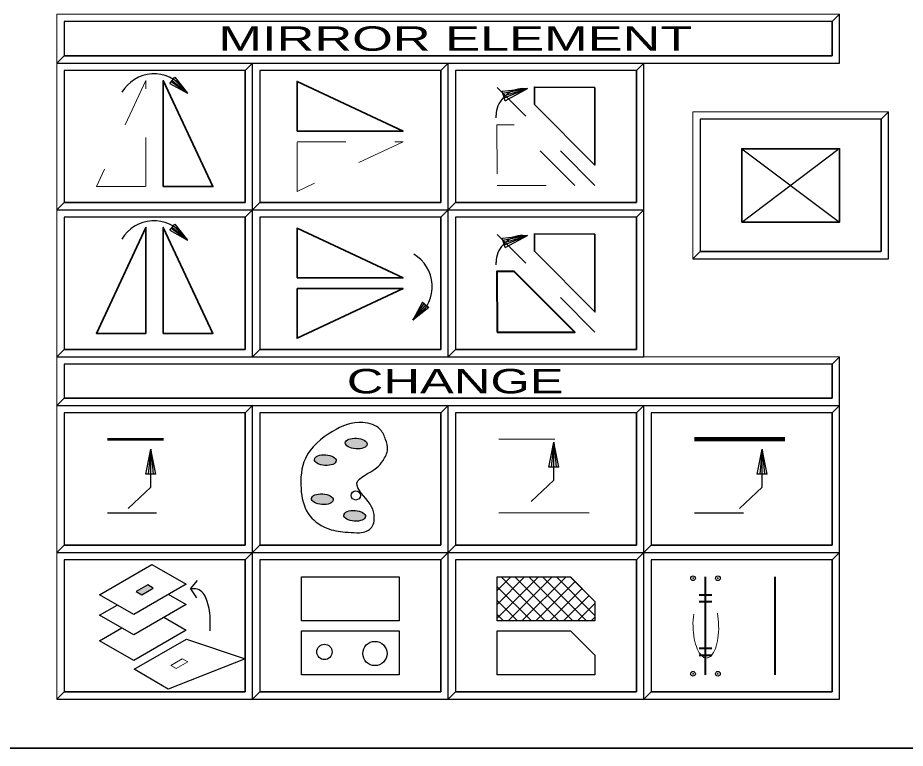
# Model space of a CAD drawing. Extents: x 95906.8 to 95923.6, y 90964.8 to 90972.8.
# Drawn here: x 95912.552 to 95914.367, y 90964.762 to 90966.254 of the extents above; entities that cross this region are included whole.
import ezdxf
from ezdxf.enums import TextEntityAlignment as Align

# ---------------------------------------------------------------- set-up
doc = ezdxf.new("R2010")
doc.units = 0
doc.header["$LTSCALE"] = 0.019
doc.header["$PDMODE"] = 32
doc.header["$PDSIZE"] = 0.0095
doc.linetypes.add('LONG_DASHED', pattern=[7.5, 6, -1.5])
doc.linetypes.add('MEDIUM_DASHED', pattern=[4.5, 3, -1.5])
for name, color, linetype, lineweight in [('11', 7, 'Continuous', 25), ('12', 7, 'Continuous', 25), ('16', 7, 'Continuous', 25), ('18', 7, 'Continuous', 25), ('2', 7, 'Continuous', 13), ('3', 7, 'Continuous', 25), ('6', 7, 'Continuous', 25), ('7', 7, 'Continuous', 35)]:
    doc.layers.add(name, color=color, linetype=linetype, lineweight=lineweight)

msp = doc.modelspace()

# ---------------------------------------------------------------- hatches: boundary and pattern name
at = {"layer": '6'}
h = msp.add_hatch(color=256, dxfattribs=at)
edge = h.paths.add_edge_path()
edge.add_ellipse((95913.2443, 90965.3842), major_axis=(-0.0223, 0.0015), ratio=0.490241, start_angle=0, end_angle=360)
h = msp.add_hatch(color=256, dxfattribs=at)
edge = h.paths.add_edge_path()
edge.add_ellipse((95913.1812, 90965.3504), major_axis=(-0.0223, 0.0015), ratio=0.490241, start_angle=0, end_angle=360)
h = msp.add_hatch(color=256, dxfattribs=at)
edge = h.paths.add_edge_path()
edge.add_ellipse((95913.1751, 90965.2705), major_axis=(-0.0223, 0.0015), ratio=0.490241, start_angle=0, end_angle=360)
h = msp.add_hatch(color=256, dxfattribs=at)
edge = h.paths.add_edge_path()
edge.add_ellipse((95913.2412, 90965.2366), major_axis=(-0.0223, 0.0015), ratio=0.490241, start_angle=0, end_angle=360)
msp.add_hatch(color=256, dxfattribs=at).paths.add_polyline_path([(95912.8058, 90965.0753), (95912.8293, 90965.0889), (95912.8181, 90965.0953), (95912.7946, 90965.0817)])

# ---------------------------------------------------------------- linework, layer by layer
at = {"layer": '11'}
for points in [[(95913.0473, 90965.8767), (95913.4173, 90965.8767), (95913.4173, 90966.1467), (95913.0473, 90966.1467)], [(95913.4473, 90965.8767), (95913.8173, 90965.8767), (95913.8173, 90966.1467), (95913.4473, 90966.1467)], [(95912.6473, 90965.5767), (95913.0173, 90965.5767), (95913.0173, 90965.8467), (95912.6473, 90965.8467)], [(95913.0473, 90965.5767), (95913.4173, 90965.5767), (95913.4173, 90965.8467), (95913.0473, 90965.8467)], [(95913.4473, 90965.5767), (95913.8173, 90965.5767), (95913.8173, 90965.8467), (95913.4473, 90965.8467)], [(95912.6473, 90965.1767), (95913.0173, 90965.1767), (95913.0173, 90965.4467), (95912.6473, 90965.4467)], [(95913.0473, 90965.1767), (95913.4173, 90965.1767), (95913.4173, 90965.4467), (95913.0473, 90965.4467)], [(95913.4473, 90965.1767), (95913.8173, 90965.1767), (95913.8173, 90965.4467), (95913.4473, 90965.4467)], [(95912.6473, 90964.8767), (95913.0173, 90964.8767), (95913.0173, 90965.1467), (95912.6473, 90965.1467)], [(95913.0473, 90964.8767), (95913.4173, 90964.8767), (95913.4173, 90965.1467), (95913.0473, 90965.1467)], [(95913.4473, 90964.8767), (95913.8173, 90964.8767), (95913.8173, 90965.1467), (95913.4473, 90965.1467)], [(95913.8473, 90964.8767), (95914.2173, 90964.8767), (95914.2173, 90965.1467), (95913.8473, 90965.1467)]]:
    msp.add_lwpolyline(points, close=True, dxfattribs=at)
at = {"layer": '12'}
for points in [[(95912.6473, 90965.8767), (95913.0173, 90965.8767), (95913.0173, 90966.1467), (95912.6473, 90966.1467)], [(95913.8473, 90965.1767), (95914.2173, 90965.1767), (95914.2173, 90965.4467), (95913.8473, 90965.4467)]]:
    msp.add_lwpolyline(points, close=True, dxfattribs=at)
at = {"layer": '16'}
msp.add_lwpolyline([(95913.9473, 90965.7767), (95914.3173, 90965.7767), (95914.3173, 90966.0467), (95913.9473, 90966.0467)], close=True, dxfattribs=at)
at = {"layer": '18'}
for points in [[(95912.6473, 90966.1767), (95914.2173, 90966.1767), (95914.2173, 90966.2467), (95912.6473, 90966.2467)], [(95912.6473, 90965.4767), (95914.2173, 90965.4767), (95914.2173, 90965.5467), (95912.6473, 90965.5467)]]:
    msp.add_lwpolyline(points, close=True, dxfattribs=at)
at = {"layer": '2'}
for points in [[(95912.6323, 90966.2617), (95912.6323, 90966.1617), (95912.6473, 90966.1767), (95912.6473, 90966.2467), (95914.2173, 90966.2467), (95914.2323, 90966.2617)], [(95912.6323, 90966.1617), (95912.6323, 90965.8617), (95912.6473, 90965.8767), (95912.6473, 90966.1467), (95913.0173, 90966.1467), (95913.0323, 90966.1617)], [(95913.0323, 90966.1617), (95913.0323, 90965.8617), (95913.0473, 90965.8767), (95913.0473, 90966.1467), (95913.4173, 90966.1467), (95913.4323, 90966.1617)], [(95913.4323, 90966.1617), (95913.4323, 90965.8617), (95913.4473, 90965.8767), (95913.4473, 90966.1467), (95913.8173, 90966.1467), (95913.8323, 90966.1617)], [(95913.9323, 90966.0617), (95913.9323, 90965.7617), (95913.9473, 90965.7767), (95913.9473, 90966.0467), (95914.3173, 90966.0467), (95914.3323, 90966.0617)], [(95912.6323, 90965.8617), (95912.6323, 90965.5617), (95912.6473, 90965.5767), (95912.6473, 90965.8467), (95913.0173, 90965.8467), (95913.0323, 90965.8617)], [(95913.0323, 90965.8617), (95913.0323, 90965.5617), (95913.0473, 90965.5767), (95913.0473, 90965.8467), (95913.4173, 90965.8467), (95913.4323, 90965.8617)], [(95913.4323, 90965.8617), (95913.4323, 90965.5617), (95913.4473, 90965.5767), (95913.4473, 90965.8467), (95913.8173, 90965.8467), (95913.8323, 90965.8617)], [(95912.6323, 90965.5617), (95912.6323, 90965.4617), (95912.6473, 90965.4767), (95912.6473, 90965.5467), (95914.2173, 90965.5467), (95914.2323, 90965.5617)], [(95912.6323, 90965.4617), (95912.6323, 90965.1617), (95912.6473, 90965.1767), (95912.6473, 90965.4467), (95913.0173, 90965.4467), (95913.0323, 90965.4617)], [(95913.0323, 90965.4617), (95913.0323, 90965.1617), (95913.0473, 90965.1767), (95913.0473, 90965.4467), (95913.4173, 90965.4467), (95913.4323, 90965.4617)], [(95913.4323, 90965.4617), (95913.4323, 90965.1617), (95913.4473, 90965.1767), (95913.4473, 90965.4467), (95913.8173, 90965.4467), (95913.8323, 90965.4617)], [(95913.8323, 90965.4617), (95913.8323, 90965.1617), (95913.8473, 90965.1767), (95913.8473, 90965.4467), (95914.2173, 90965.4467), (95914.2323, 90965.4617)], [(95912.6323, 90965.1617), (95912.6323, 90964.8617), (95912.6473, 90964.8767), (95912.6473, 90965.1467), (95913.0173, 90965.1467), (95913.0323, 90965.1617)], [(95913.0323, 90965.1617), (95913.0323, 90964.8617), (95913.0473, 90964.8767), (95913.0473, 90965.1467), (95913.4173, 90965.1467), (95913.4323, 90965.1617)], [(95913.4323, 90965.1617), (95913.4323, 90964.8617), (95913.4473, 90964.8767), (95913.4473, 90965.1467), (95913.8173, 90965.1467), (95913.8323, 90965.1617)], [(95913.8323, 90965.1617), (95913.8323, 90964.8617), (95913.8473, 90964.8767), (95913.8473, 90965.1467), (95914.2173, 90965.1467), (95914.2323, 90965.1617)]]:
    msp.add_lwpolyline(points, close=True, dxfattribs=at)
at = {"layer": '3'}
for points in [[(95912.6323, 90966.1617), (95914.2323, 90966.1617), (95914.2323, 90966.2617), (95914.2173, 90966.2467), (95914.2173, 90966.1767), (95912.6473, 90966.1767)], [(95912.6323, 90965.8617), (95913.0323, 90965.8617), (95913.0323, 90966.1617), (95913.0173, 90966.1467), (95913.0173, 90965.8767), (95912.6473, 90965.8767)], [(95913.0323, 90965.8617), (95913.4323, 90965.8617), (95913.4323, 90966.1617), (95913.4173, 90966.1467), (95913.4173, 90965.8767), (95913.0473, 90965.8767)], [(95913.4323, 90965.8617), (95913.8323, 90965.8617), (95913.8323, 90966.1617), (95913.8173, 90966.1467), (95913.8173, 90965.8767), (95913.4473, 90965.8767)], [(95913.9323, 90965.7617), (95914.3323, 90965.7617), (95914.3323, 90966.0617), (95914.3173, 90966.0467), (95914.3173, 90965.7767), (95913.9473, 90965.7767)], [(95912.6323, 90965.5617), (95913.0323, 90965.5617), (95913.0323, 90965.8617), (95913.0173, 90965.8467), (95913.0173, 90965.5767), (95912.6473, 90965.5767)], [(95913.0323, 90965.5617), (95913.4323, 90965.5617), (95913.4323, 90965.8617), (95913.4173, 90965.8467), (95913.4173, 90965.5767), (95913.0473, 90965.5767)], [(95913.4323, 90965.5617), (95913.8323, 90965.5617), (95913.8323, 90965.8617), (95913.8173, 90965.8467), (95913.8173, 90965.5767), (95913.4473, 90965.5767)], [(95912.6323, 90965.4617), (95914.2323, 90965.4617), (95914.2323, 90965.5617), (95914.2173, 90965.5467), (95914.2173, 90965.4767), (95912.6473, 90965.4767)], [(95912.6323, 90965.1617), (95913.0323, 90965.1617), (95913.0323, 90965.4617), (95913.0173, 90965.4467), (95913.0173, 90965.1767), (95912.6473, 90965.1767)], [(95913.0323, 90965.1617), (95913.4323, 90965.1617), (95913.4323, 90965.4617), (95913.4173, 90965.4467), (95913.4173, 90965.1767), (95913.0473, 90965.1767)], [(95913.4323, 90965.1617), (95913.8323, 90965.1617), (95913.8323, 90965.4617), (95913.8173, 90965.4467), (95913.8173, 90965.1767), (95913.4473, 90965.1767)], [(95913.8323, 90965.1617), (95914.2323, 90965.1617), (95914.2323, 90965.4617), (95914.2173, 90965.4467), (95914.2173, 90965.1767), (95913.8473, 90965.1767)], [(95912.6323, 90964.8617), (95913.0323, 90964.8617), (95913.0323, 90965.1617), (95913.0173, 90965.1467), (95913.0173, 90964.8767), (95912.6473, 90964.8767)], [(95913.0323, 90964.8617), (95913.4323, 90964.8617), (95913.4323, 90965.1617), (95913.4173, 90965.1467), (95913.4173, 90964.8767), (95913.0473, 90964.8767)], [(95913.4323, 90964.8617), (95913.8323, 90964.8617), (95913.8323, 90965.1617), (95913.8173, 90965.1467), (95913.8173, 90964.8767), (95913.4473, 90964.8767)], [(95913.8323, 90964.8617), (95914.2323, 90964.8617), (95914.2323, 90965.1617), (95914.2173, 90965.1467), (95914.2173, 90964.8767), (95913.8473, 90964.8767)]]:
    msp.add_lwpolyline(points, close=True, dxfattribs=at)
at = {"layer": '6'}
for p, q in [((95912.8997, 90966.0999), (95912.8659, 90966.1233)), ((95912.8683, 90966.1262), (95912.8997, 90966.0999)), ((95913.5457, 90966.0944), (95913.5947, 90966.1094)), ((95913.5947, 90966.1094), (95913.5471, 90966.0899)), ((95913.5846, 90966.1094), (95913.5947, 90966.1094)), ((95913.5447, 90966.0902), (95913.5493, 90966.0948)), ((95913.5301, 90966.0495), (95913.5301, 90966.0549)), ((95914.0323, 90965.9867), (95914.2323, 90965.8367)), ((95914.0323, 90965.8367), (95914.2287, 90965.9852)), ((95912.8997, 90965.7999), (95912.8659, 90965.8233)), ((95912.8683, 90965.8262), (95912.8997, 90965.7999)), ((95913.5457, 90965.7944), (95913.5947, 90965.8094)), ((95913.5947, 90965.8094), (95913.5471, 90965.7899)), ((95913.5846, 90965.8094), (95913.5947, 90965.8094)), ((95913.5447, 90965.7902), (95913.5493, 90965.7948)), ((95913.5301, 90965.7495), (95913.5301, 90965.7549)), ((95913.36, 90965.6364), (95913.3834, 90965.6702)), ((95913.3863, 90965.6678), (95913.36, 90965.6364)), ((95913.6481, 90965.3361), (95913.6481, 90965.3873)), ((95913.6481, 90965.3873), (95913.6529, 90965.3361)), ((95912.8242, 90965.3216), (95912.8242, 90965.3728)), ((95912.8242, 90965.3728), (95912.829, 90965.3216)), ((95914.0742, 90965.3216), (95914.0742, 90965.3728)), ((95914.0742, 90965.3728), (95914.079, 90965.3216)), ((95912.9057, 90965.0875), (95912.9196, 90965.1044)), ((95912.9057, 90965.0875), (95912.918, 90965.0691)), ((95912.9124, 90965.0875), (95912.9057, 90965.0875)), ((95912.938, 90965.0659), (95912.9353, 90965.0725)), ((95912.9457, 90965.0014), (95912.9457, 90965.0275))]:
    msp.add_line(p, q, dxfattribs=at)
at = {"layer": '6', "linetype": 'MEDIUM_DASHED', "lineweight": 13}
for p, q in [((95913.7323, 90965.9117), (95913.5323, 90966.1117)), ((95913.7323, 90965.6117), (95913.5323, 90965.8117))]:
    msp.add_line(p, q, dxfattribs=at)
at = {"layer": '6', "linetype": 'LONG_DASHED', "lineweight": 53}
msp.add_line((95912.7361, 90965.393), (95912.9205, 90965.393), dxfattribs=at)
at = {"layer": '6', "linetype": 'LONG_DASHED', "lineweight": 13}
msp.add_line((95913.5361, 90965.393), (95913.7205, 90965.393), dxfattribs=at)
at = {"layer": '6', "lineweight": 158}
msp.add_line((95913.9361, 90965.393), (95914.1205, 90965.393), dxfattribs=at)
at = {"layer": '6', "linetype": 'MEDIUM_DASHED'}
for p, q in [((95912.7361, 90965.2424), (95912.9205, 90965.2424)), ((95913.9361, 90965.2424), (95914.1205, 90965.2424))]:
    msp.add_line(p, q, dxfattribs=at)
at = {"layer": '6', "lineweight": 13}
for p, q in [((95913.5361, 90965.2424), (95913.7205, 90965.2424)), ((95913.5323, 90965.0273), (95913.6167, 90965.1117)), ((95913.5323, 90965.0556), (95913.5884, 90965.1117)), ((95913.5323, 90965.0839), (95913.5601, 90965.1117)), ((95913.5406, 90965.1117), (95913.6306, 90965.0217)), ((95913.555, 90965.0217), (95913.645, 90965.1117)), ((95913.5688, 90965.1117), (95913.6588, 90965.0217)), ((95913.5832, 90965.0217), (95913.6732, 90965.1117)), ((95913.5971, 90965.1117), (95913.6871, 90965.0217)), ((95913.6254, 90965.1117), (95913.7154, 90965.0217)), ((95913.6537, 90965.1117), (95913.7323, 90965.0331)), ((95913.682, 90965.1117), (95913.7323, 90965.0614)), ((95913.6115, 90965.0217), (95913.6919, 90965.1021)), ((95913.5323, 90965.0917), (95913.6023, 90965.0217)), ((95913.6398, 90965.0217), (95913.7061, 90965.0879)), ((95913.5323, 90965.0634), (95913.574, 90965.0217)), ((95913.6681, 90965.0217), (95913.7202, 90965.0738)), ((95913.6964, 90965.0217), (95913.7323, 90965.0576)), ((95913.5323, 90965.0351), (95913.5457, 90965.0217)), ((95913.7247, 90965.0217), (95913.7323, 90965.0293))]:
    msp.add_line(p, q, dxfattribs=at)
at = {"layer": '6', "lineweight": 40}
for p, q in [((95913.9573, 90965.1117), (95913.9573, 90964.9117)), ((95914.1003, 90965.1117), (95914.1003, 90964.9117)), ((95913.9451, 90965.0752), (95913.9713, 90965.0752)), ((95913.9451, 90965.0614), (95913.9713, 90965.0614)), ((95913.9451, 90964.9661), (95913.9713, 90964.9661)), ((95913.9451, 90964.9522), (95913.9713, 90964.9522))]:
    msp.add_line(p, q, dxfattribs=at)
at = {"layer": '6'}
for points in [[(95912.8631, 90966.12), (95912.8736, 90966.1325), (95912.8997, 90966.0999)], [(95912.8631, 90966.12), (95912.8997, 90966.0999), (95912.8709, 90966.1293)], [(95913.5487, 90966.0846), (95913.5427, 90966.1042), (95913.5947, 90966.1094)], [(95913.5487, 90966.0846), (95913.5947, 90966.1094), (95913.5443, 90966.0992)], [(95912.8631, 90965.82), (95912.8736, 90965.8325), (95912.8997, 90965.7999)], [(95912.8631, 90965.82), (95912.8997, 90965.7999), (95912.8709, 90965.8293)], [(95913.5487, 90965.7846), (95913.5427, 90965.8042), (95913.5947, 90965.8094)], [(95913.5487, 90965.7846), (95913.5947, 90965.8094), (95913.5443, 90965.7992)], [(95913.3801, 90965.673), (95913.3926, 90965.6625), (95913.36, 90965.6364)], [(95913.3801, 90965.673), (95913.36, 90965.6364), (95913.3894, 90965.6652)], [(95913.6018, 90965.2659), (95913.6481, 90965.3093), (95913.6481, 90965.3873)], [(95913.6583, 90965.3361), (95913.6379, 90965.3361), (95913.6481, 90965.3873)], [(95913.6583, 90965.3361), (95913.6481, 90965.3873), (95913.6431, 90965.3361)], [(95912.7779, 90965.2514), (95912.8242, 90965.2948), (95912.8242, 90965.3728)], [(95912.8344, 90965.3216), (95912.814, 90965.3216), (95912.8242, 90965.3728)], [(95912.8344, 90965.3216), (95912.8242, 90965.3728), (95912.8192, 90965.3216)], [(95914.0279, 90965.2514), (95914.0742, 90965.2948), (95914.0742, 90965.3728)], [(95914.0844, 90965.3216), (95914.064, 90965.3216), (95914.0742, 90965.3728)], [(95914.0844, 90965.3216), (95914.0742, 90965.3728), (95914.0692, 90965.3216)], [(95912.8602, 90965.0763), (95912.8965, 90965.0552), (95912.7895, 90964.9934), (95912.7197, 90965.0337), (95912.7554, 90965.0543)], [(95912.8511, 90965.0292), (95912.8965, 90965.0029), (95912.7895, 90964.9411), (95912.7197, 90964.9814), (95912.765, 90965.0076)]]:
    msp.add_lwpolyline(points, dxfattribs=at)
at = {"layer": '6', "linetype": 'MEDIUM_DASHED', "lineweight": 13}
for points in [[(95912.8146, 90965.9093), (95912.8146, 90966.126), (95912.7132, 90965.9093)], [(95913.5323, 90965.9117), (95913.6909, 90965.9117), (95913.567, 90966.0356), (95913.5317, 90966.0356)], [(95913.1234, 90966.0007), (95913.3401, 90966.0007), (95913.1234, 90965.8993)], [(95912.8765, 90964.9246), (95912.9, 90964.9382), (95912.8888, 90964.9446), (95912.8653, 90964.931)]]:
    msp.add_lwpolyline(points, close=True, dxfattribs=at)
at = {"layer": '6', "lineweight": 35}
for points in [[(95912.85, 90965.9093), (95912.85, 90966.126), (95912.9514, 90965.9093)], [(95913.1234, 90966.0227), (95913.3401, 90966.0227), (95913.1234, 90966.1241)], [(95913.7324, 90966.1118), (95913.7324, 90965.9532), (95913.6085, 90966.0771), (95913.6085, 90966.1124)], [(95914.0323, 90965.8367), (95914.2323, 90965.8367), (95914.2323, 90965.9867), (95914.0323, 90965.9867)], [(95912.8146, 90965.6093), (95912.8146, 90965.826), (95912.7132, 90965.6093)], [(95912.85, 90965.6093), (95912.85, 90965.826), (95912.9514, 90965.6093)], [(95913.1234, 90965.7227), (95913.3401, 90965.7227), (95913.1234, 90965.8241)], [(95913.7324, 90965.8118), (95913.7324, 90965.6532), (95913.6085, 90965.7771), (95913.6085, 90965.8124)], [(95913.1234, 90965.7007), (95913.3401, 90965.7007), (95913.1234, 90965.5993)]]:
    msp.add_lwpolyline(points, close=True, dxfattribs=at)
at = {"layer": '6', "lineweight": 40}
msp.add_lwpolyline([(95913.5323, 90965.6117), (95913.6909, 90965.6117), (95913.567, 90965.7356), (95913.5317, 90965.7356)], close=True, dxfattribs=at)
at = {"layer": '6'}
for points in [[(95912.7197, 90965.0752), (95912.8267, 90965.137), (95912.8965, 90965.0967), (95912.7895, 90965.0349)], [(95913.1323, 90965.1117), (95913.3323, 90965.1117), (95913.3323, 90965.0217), (95913.1323, 90965.0217)], [(95913.5323, 90965.1117), (95913.6823, 90965.1117), (95913.7323, 90965.0617), (95913.7323, 90965.0217), (95913.5323, 90965.0217)], [(95912.8058, 90965.0753), (95912.8293, 90965.0889), (95912.8181, 90965.0953), (95912.7946, 90965.0817)], [(95913.1323, 90965.0017), (95913.3323, 90965.0017), (95913.3323, 90964.9117), (95913.1323, 90964.9117)], [(95913.5323, 90965.0017), (95913.6823, 90965.0017), (95913.7323, 90964.9517), (95913.7323, 90964.9117), (95913.5323, 90964.9117)], [(95912.7904, 90964.923), (95912.8974, 90964.9848), (95913.0172, 90964.9445), (95912.8602, 90964.8827)]]:
    msp.add_lwpolyline(points, close=True, dxfattribs=at)
for centre, radius in [((95913.2435, 90965.2782), 0.00934), ((95913.1794, 90964.9585), 0.0157), ((95913.2825, 90964.9553), 0.0248)]:
    msp.add_circle(centre, radius, dxfattribs=at)
for centre, radius, start, end in [((95912.8311, 90966.0628), 0.0767, 37.7752, 149.3662), ((95913.5846, 90966.0594), 0.05, 90, 135), ((95913.5801, 90966.0549), 0.05, 135, 180), ((95912.8311, 90965.7628), 0.0767, 37.7752, 149.3662), ((95913.5846, 90965.7594), 0.05, 90, 135), ((95913.5801, 90965.7549), 0.05, 135, 180), ((95913.3229, 90965.705), 0.0767, 307.7753, 59.3661), ((95912.9124, 90965.0625), 0.025, 23.5654, 90), ((95912.8457, 90965.0275), 0.1, 0, 22.5992)]:
    msp.add_arc(centre, radius, start, end, dxfattribs=at)
for centre in [(95913.2443, 90965.3842), (95913.1812, 90965.3504), (95913.1751, 90965.2705), (95913.2412, 90965.2366)]:
    msp.add_ellipse(centre, major_axis=(-0.0223, 0.0015), ratio=0.490241, dxfattribs=at)
at = {"layer": '6', "linetype": 'MEDIUM_DASHED', "lineweight": 13}
msp.add_ellipse((95913.959, 90965.0115), major_axis=(0.0015, -0.0654), ratio=0.400869, dxfattribs=at)
at = {"layer": '6'}
msp.add_spline([(95913.2456, 90965.202), (95913.2218, 90965.2034), (95913.184, 90965.2114), (95913.1462, 90965.2415), (95913.1315, 90965.2918), (95913.1405, 90965.3537), (95913.1959, 90965.4091), (95913.2577, 90965.4273), (95913.2935, 90965.4129), (95913.3045, 90965.3928), (95913.3085, 90965.3724), (95913.2992, 90965.3497), (95913.2858, 90965.3343), (95913.2459, 90965.3035), (95913.2727, 90965.2603), (95913.2808, 90965.2392), (95913.2761, 90965.2131), (95913.2513, 90965.202), (95913.2456, 90965.202)], degree=3, dxfattribs=at)
for p in [(95913.9328, 90965.109), (95913.9836, 90965.109), (95913.9328, 90964.9138), (95913.9836, 90964.9138)]:
    msp.add_point(p, dxfattribs=at)
at = {"layer": '7'}
msp.add_lwpolyline([(95906.8323, 90972.7617), (95918.8323, 90972.7617), (95918.8323, 90964.7617), (95906.8323, 90964.7617)], close=True, dxfattribs=at)

# ---------------------------------------------------------------- texts
for s, width, p in [('     MIRROR ELEMENT    ', 1.6, (95913.4322, 90966.1867)), ('         CHANGE        ', 1.55, (95913.4323, 90965.4867))]:
    msp.add_text(s, height=0.04999, dxfattribs=dict(at, width=width)).set_placement(p, align=Align.CENTER)

doc.saveas('drawing.dxf')
